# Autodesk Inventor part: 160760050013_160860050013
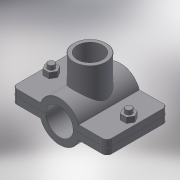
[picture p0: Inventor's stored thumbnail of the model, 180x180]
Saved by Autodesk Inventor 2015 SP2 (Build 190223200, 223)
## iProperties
Created: 2017-05
Part Number: 160760050013_160860050013
Material: Generic
Description: PLASSON SADDLE 50-1.1/4"
Document SubType Name: Modeling
Designer: KIM
Density: 1 g/cm^3
Appearance: Default
Author: KIM
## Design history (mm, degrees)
derived "16076.ipt"
feature "Solid1::16076.ipt"
feature "Solid2::16076.ipt"
tag "TaggingFeature1"
body "Solid1"
other parameters: "d1" = 106, "d2" = 25, "d4" = 73, "d5" = 0, "d6" = 5.3, "d7" = 106, "d8" = 0.1, "d10" = 0, "d11" = 0.5, "d14" = 50.6376, "d20" = 0.5, "d23" = 0.5, "d37" = 8, "d38" = 33, "d39" = 0, "d40" = 3, "d41" = 5, "d42" = 0, "d43" = 6, "d44" = 3, "d45" = 0, "d46" = 0.5, "d51" = 58, "d52" = 38.952, "d53" = 25, "d54" = 0, "d55" = 25, "d57" = 0, "d58" = 54, "d60" = 0, "d63" = 36.5, "d66" = 0, "B_" = 25, "G_" = 38.952, "A_" = 58, "L_" = 106, "L_1" = 73, "l_2" = 25
